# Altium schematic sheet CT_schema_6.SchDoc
size 255 x 245 mm
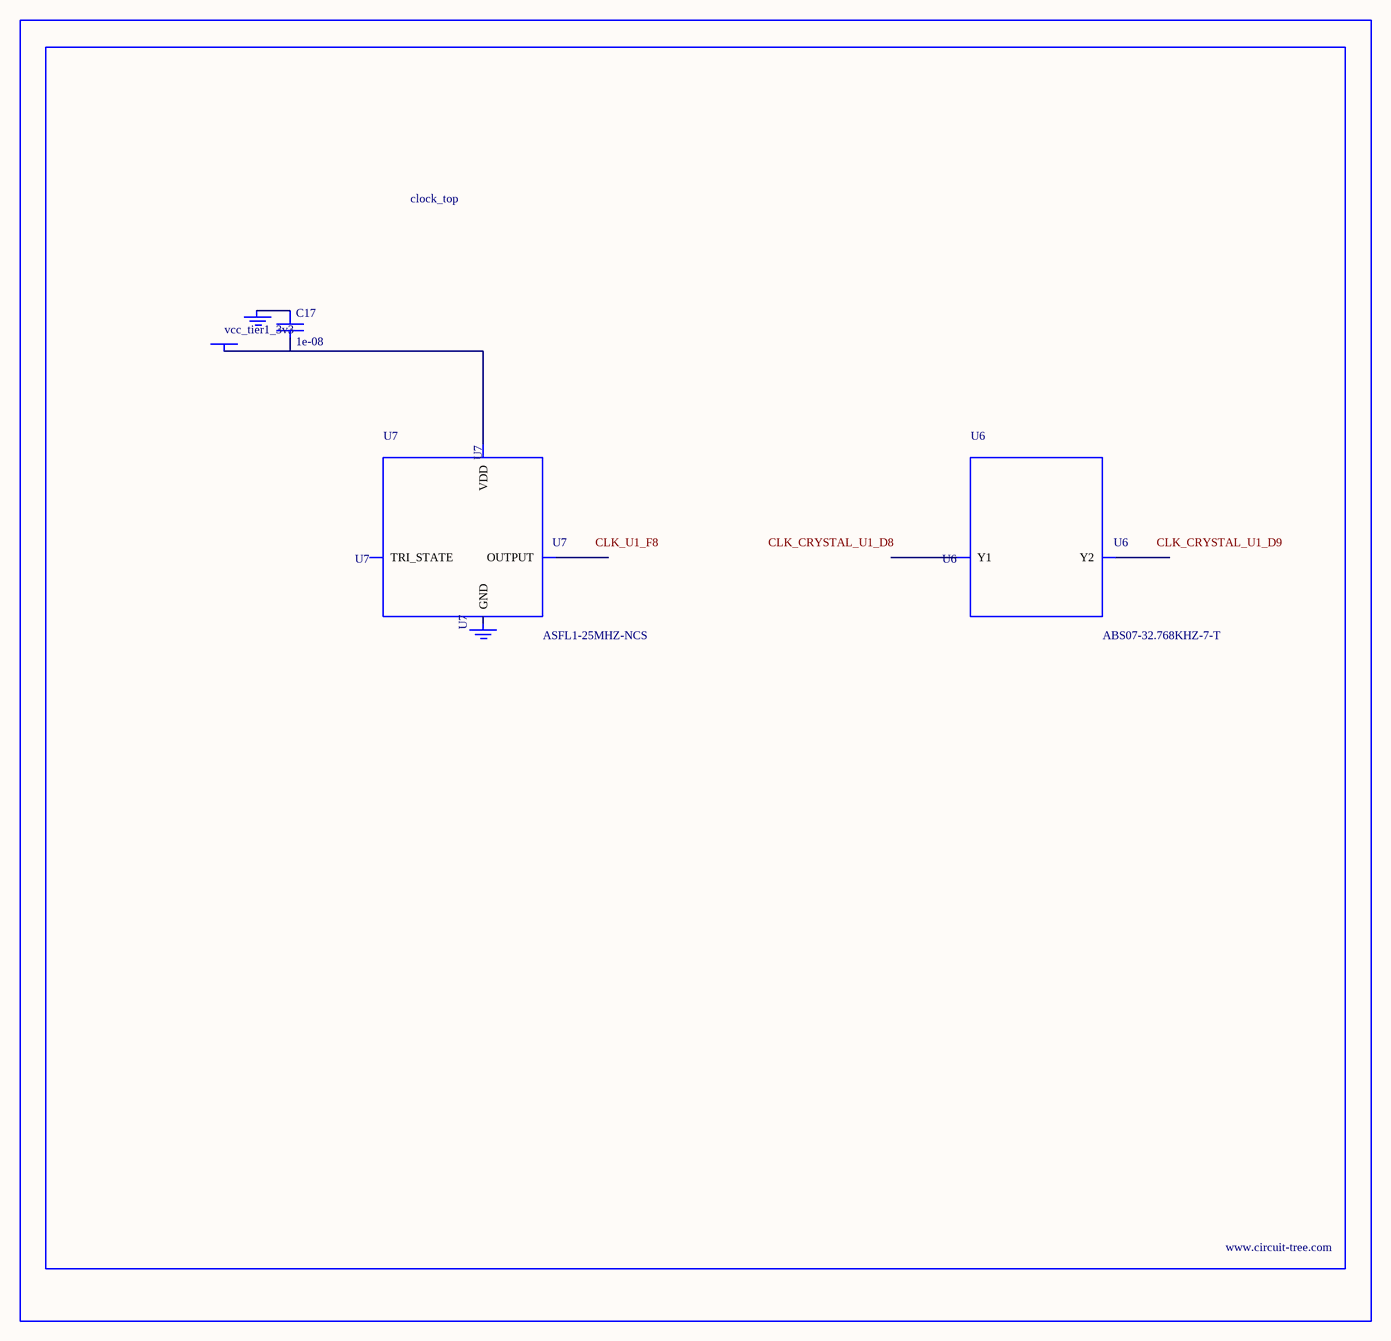
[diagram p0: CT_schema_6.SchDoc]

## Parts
BORDER5  (no value)
C17  1e-08  [C0402]
GND_INSTANCE_5_0  (no value)
GND_INSTANCE_5_1  (no value)
POWER_INSTANCE_5_0  vcc_tier1_3v3
U6  ABS07-32.768KHZ-7-T  [ABS07-32.768KHZ-7-T]
U7  ASFL1-25MHZ-NCS  [ASFL1]

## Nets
NetC17_1: C17.1 GND_INSTANCE_5_0.0(GND)
NetC17_2: C17.2 POWER_INSTANCE_5_0.0(PWR) U7.4(VDD)

Not connected (* = marked no-connect by the designer): GND_INSTANCE_5_1 0(GND); U6 1(Y1) 2(Y2); U7 1(TRI_STATE) 2(GND) 3(OUTPUT)

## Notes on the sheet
- Labels drawn without touching a wire or pin: CLK_CRYSTAL_U1_D8, CLK_CRYSTAL_U1_D9, CLK_U1_F8

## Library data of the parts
BORDER5 = BORDER_PAGE5
C17 = C0402C103K3RAC
GND_INSTANCE_5_0 GND_INSTANCE_5_1 = GND
POWER_INSTANCE_5_0 = PWR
